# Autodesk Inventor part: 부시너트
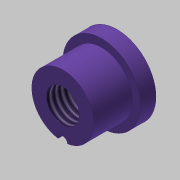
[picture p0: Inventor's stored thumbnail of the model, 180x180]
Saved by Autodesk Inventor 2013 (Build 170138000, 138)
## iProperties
Created: 2020-03
Part Number: 부시너트
Material: 스테인리스강
Document SubType Name: Modeling
Designer: mduedu
Density: 1 g/cm^3
Author: mduedu
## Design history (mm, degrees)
sketch "스케치1"
  geometry: L1 (0, 0)-(10, 0); L2 (10, 0)-(10, 8); L3 (10, 8)-(0, 8); L4 (0, 8)-(0, 0); L5 (10, 0)-(14, 0); L6 (14, 0)-(14, 10); L7 (14, 10)-(10, 10); L8 (10, 10)-(10, 0)
  constraints: 16 end point, 4 parallel, 2 horizontal, 2 perpendicular
  dimensions: "d0" = 14 distance between parallel lines of L6 L4; "d2" = 16 diameter of L3 L1; "d3" = 20 diameter of L7 L5; "d4" = 4 distance of L6.end L7.end
revolve "회전1" sketch "스케치1" stored, may be unused: angle "d5" = 90 deg
hole "구멍1" diameter "d8" = 8.5; stored, may be unused: countersink angle "d12" = 90 deg, drill point angle "d14" = 118 deg; dims "d9" = 6, "d10" = 4, "d11" = 2, "d13" = 8, "d15" = 10, "d16" = 10
sketch "스케치2"
  geometry: 3 further points
  constraints: 2 vertical alignment, 1 other
hole "구멍2" sketch "스케치2" at (0, -8) diameter "d17" = 2.459; stored, may be unused: countersink angle "d21" = 90 deg, drill point angle "d23" = 118 deg; dims "d18" = 5, "d19" = 4, "d20" = 2, "d22" = 7
node "솔리드1"
